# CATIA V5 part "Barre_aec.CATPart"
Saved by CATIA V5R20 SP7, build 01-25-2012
Part number: Barre_aec
Bounding box of the stored display mesh (mm): x 5 to 20, y -5.999 to 55.999, z -5.992 to 92.595
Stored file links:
  G:\bon\Nouveau dossier\Barre_aec.CATPart
  G:\bon\Nouveau dossier\cgirerd.CATProduct
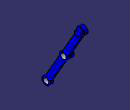
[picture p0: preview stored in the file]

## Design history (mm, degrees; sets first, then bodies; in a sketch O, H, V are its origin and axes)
Set1
  Point1 "E": linked copy from another document
  Point2 "A": linked copy from another document
  Point3 "C": linked copy from another document
Body1 (main body)
  Sketch1 on yz-plane, origin (0, 0, 0), H (0, 1, 0), V (0, 0, 1)
    circle A1 centre (25, 43.3013) radius 6
    point P1 (25, 43.3013)
    reference projected point E1 (25, 43.3013) from Point1
    radius A1 = 6
    coincidence: P1 E1
  Pad1: profile Sketch1, direction (1, 0, 0), length 10, opposite side length -5
  Sketch2 on end face of Pad1, origin (10, 0, 0), H (0, 1, 0), V (0, 0, 1)
    arc A1 centre (25, 43.3013) radius 6 from (23.772, 49.1743) to (19.2998, 41.4283) ccw
    point P1 (25, 43.3013)
    reference projected point E1 (25, 43.3013) from Point1
    arc A2 centre (0, 0) radius 6 from (-1.228, 5.873) to (5.7002, 1.873) ccw
    point P2 (0, 0)
    reference projected point E2 (0, 0) from Point2
    line L1 (5.7002, 1.873) -> (26.228, 37.4283)
    arc A3 centre (50, 86.6025) radius 6 from (51.228, 80.7296) to (44.2998, 84.7296) ccw
    point P3 (50, 86.6025)
    reference projected point E3 (50, 86.6025) from Point3
    point P6 (30.7002, 45.1743)
    arc A4 centre (25, 43.3013) radius 6 from (26.228, 37.4283) to (30.7002, 45.1743) ccw
    line L2 (23.772, 49.1743) -> (44.2998, 84.7296)
    line L3 (30.7002, 45.1743) -> (51.228, 80.7296)
    line L4 (-1.228, 5.873) -> (19.2998, 41.4283)
    radius A1 = 6
    radius A2 = 6
    radius A3 = 6
    distance L2 L3 = 8
    distance P3 L3 = 4
    distance L1 P2 = 4
    coincidence: P1 E1, P2 E2, P3 E3, L1 P6, A1 A4, L1 L3, L4 L2
    parallelism: L4 L1
  Pad2: profile Sketch2, direction (1, 0, 0), length 5
  Sketch3 on end face of Pad2, origin (15, 0, 0), H (0, 1, 0), V (0, 0, 1)
    circle A1 centre (25, 43.3013) radius 4
    point P1 (25, 43.3013)
    reference projected point E1 (25, 43.3013) from Point1
    radius A1 = 4
    coincidence: P1 E1
  Pocket1: profile Sketch3, direction (-1, 0, 0), length 10
  Sketch4 on end face of Pad2, origin (15, 0, 0), H (0, 1, 0), V (0, 0, 1)
    circle A1 centre (0, 0) radius 4
    point P1 (0, 0)
    reference projected point E1 (0, 0) from Point2
    radius A1 = 4
    coincidence: P1 E1
  Pocket2: profile Sketch4, direction (-1, 0, 0), length 5
  Sketch5 on end face of Pad2, origin (15, 0, 0), H (0, 1, 0), V (0, 0, 1)
    circle A1 centre (50, 86.6025) radius 4
    point P1 (50, 86.6025)
    reference projected point E1 (50, 86.6025) from Point3
    radius A1 = 4
    coincidence: P1 E1
  Pad3: profile Sketch5, direction (1, 0, 0), length 5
